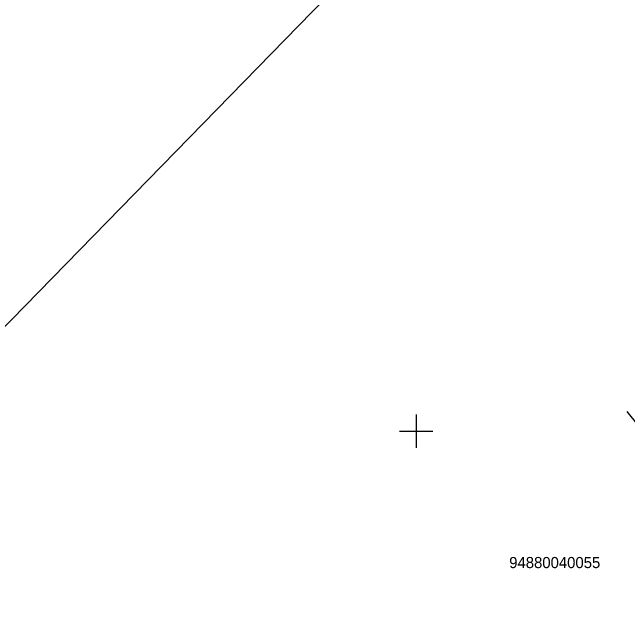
# Model space of a CAD drawing. Extents: x 616607 to 617499, y 408385 to 409695.
# Drawn here: x 617313.7 to 617369, y 409583.6 to 409637.6 of the extents above; entities that cross this region are included whole.
import ezdxf

# ---------------------------------------------------------------- set-up
doc = ezdxf.new("R2010")
doc.units = 0
for name, color, linetype in [('GEOD_ELEM_####_####_#', 7, 'Continuous'), ('RAMI_PLAN_####_TKST_#', 7, 'Continuous'), ('RELJ_NOGA_####_####_#', 7, 'Continuous'), ('ROBZ_IERR_####_####_#', 7, 'Continuous'), ('ROBZ_IERR_####_TKST_#', 7, 'Continuous')]:
    doc.layers.add(name, color=color, linetype=linetype)

# ---------------------------------------------------------------- blocks, each defined once
blk = doc.blocks.new('KRUSTS')
at = {"layer": 'GEOD_ELEM_####_####_#'}
for p, q in [((0, 1.5), (0, 0)), ((-1.5, 0), (0, 0)), ((0, 0), (0, -1.5)), ((0, 0), (1.5, 0))]:
    blk.add_line(p, q, dxfattribs=at)

msp = doc.modelspace()

# ---------------------------------------------------------------- linework, layer by layer
at = {"layer": 'RAMI_PLAN_####_TKST_#'}
msp.add_line((617025.875, 409315.482), (617396.817, 409695.175), dxfattribs=at)
at = {"layer": 'RELJ_NOGA_####_####_#'}
for points in [[(617340.777, 409537.001), (617341.078, 409537.005), (617341.378, 409537.016), (617341.678, 409537.028), (617342.308, 409537.052), (617342.934, 409537.126), (617343.561, 409537.2), (617344.196, 409537.274), (617344.821, 409537.394), (617345.442, 409537.561), (617345.753, 409537.644), (617346.049, 409537.762), (617346.339, 409537.902), (617346.489, 409537.973), (617346.63, 409538.054), (617346.772, 409538.138), (617346.919, 409538.225), (617347.057, 409538.319), (617347.191, 409538.428), (617347.493, 409538.675), (617347.758, 409538.966), (617347.918, 409539.317), (617348.078, 409539.667), (617348.21, 409540.021), (617348.343, 409540.379), (617348.475, 409540.736), (617348.579, 409541.101), (617348.72, 409541.456), (617348.856, 409541.799), (617349.051, 409542.123), (617349.304, 409542.39), (617352.519, 409545.77), (617355.747, 409549.116), (617359.001, 409552.447), (617362.259, 409555.782), (617365.506, 409559.128), (617368.776, 409562.45), (617375.323, 409569.103), (617381.891, 409575.733), (617388.441, 409582.383), (617394.992, 409589.035), (617401.535, 409595.694), (617408.065, 409602.367), (617411.328, 409605.701), (617414.56, 409609.066), (617417.789, 409612.434), (617421.016, 409615.8), (617424.21, 409619.196), (617427.415, 409622.582), (617427.788, 409622.976), (617428.152, 409623.378), (617428.521, 409623.775), (617428.615, 409623.876), (617428.734, 409623.953), (617428.829, 409624.052), (617428.856, 409624.08), (617428.859, 409624.145), (617428.829, 409624.171), (617428.532, 409624.429), (617428.227, 409624.676), (617427.914, 409624.914), (617427.604, 409625.151), (617427.298, 409625.391), (617426.983, 409625.621), (617426.355, 409626.078), (617425.721, 409626.524), (617425.072, 409626.95), (617424.42, 409627.378), (617423.762, 409627.796), (617423.101, 409628.211), (617422.43, 409628.633), (617421.754, 409629.042), (617421.074, 409629.457), (617420.952, 409629.531), (617420.825, 409629.61), (617420.7, 409629.662), (617420.6, 409629.703), (617420.471, 409629.604), (617420.39, 409629.526), (617415.561, 409624.878), (617410.732, 409620.23), (617405.903, 409615.582)], [(617405.903, 409615.582), (617390.969, 409600.632), (617376.035, 409585.682), (617361.1, 409570.732), (617353.162, 409562.786), (617345.334, 409554.728), (617337.455, 409546.726), (617337.388, 409546.658), (617337.328, 409546.458), (617337.253, 409546.519), (617336.529, 409547.109), (617335.804, 409547.698), (617335.079, 409548.288)]]:
    msp.add_open_spline(points, degree=3, dxfattribs=at)
at = {"layer": 'ROBZ_IERR_####_####_#'}
msp.add_lwpolyline([(617368.929, 409601.756), (617389.961, 409575.652), (617384.525, 409570.278), (617370.73, 409556.7), (617349.038, 409581.404)], dxfattribs=at)

# ---------------------------------------------------------------- block references
at = {"layer": 'GEOD_ELEM_####_####_#'}
msp.add_blockref('KRUSTS', (617350, 409600), dxfattribs=at)

# ---------------------------------------------------------------- texts
at = {"layer": 'ROBZ_IERR_####_TKST_#'}
msp.add_text('94880040055', height=1, dxfattribs=at).set_placement((617358.351, 409587.695))

doc.saveas('drawing.dxf')
